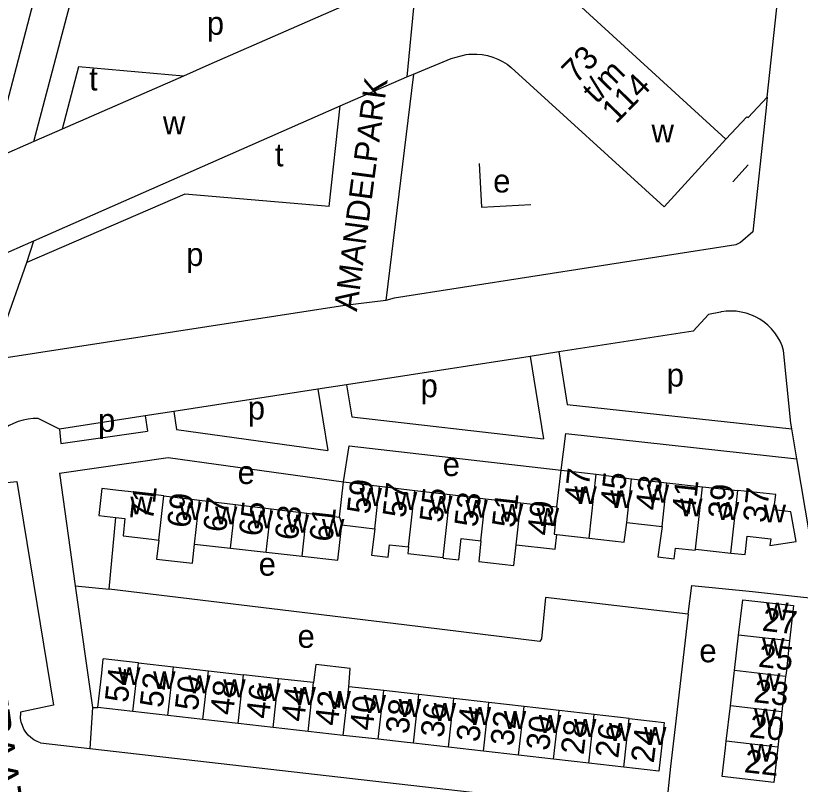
# Model space of a CAD drawing. Extents: x 161936 to 163647, y 386450 to 388633.
# Drawn here: x 162533 to 162668.3, y 387480.8 to 387613.3 of the extents above; entities that cross this region are included whole.
import ezdxf

# ---------------------------------------------------------------- set-up
doc = ezdxf.new("R2010")
doc.units = 0
for name, color, linetype in [('BLT_Basislijn', 7, 'Continuous'), ('BLT_Bebouwing', 7, 'Continuous'), ('BLT_Centroide', 7, 'Continuous'), ('BLT_Huisnummer', 7, 'Continuous'), ('BLT_Huisnummer_ tussenligend', 7, 'Continuous'), ('BLT_Huisnummer_reeks', 7, 'Continuous'), ('BLT_Onderdoorgang_en_onderverdeling', 7, 'Continuous'), ('BLT_Onderverdeling_panden', 7, 'Continuous'), ('BLT_Straatnaam', 7, 'Continuous')]:
    doc.layers.add(name, color=color, linetype=linetype)

msp = doc.modelspace()

# ---------------------------------------------------------------- linework, layer by layer
at = {"layer": 'BLT_Basislijn'}
for p, q in [((162536.08, 387615.52), (162528.92, 387588.41)), ((162536.17, 387591.57), (162542.39, 387615.1)), ((162601.58, 387603.19), (162596.84, 387564.21)), ((162662.59, 387599.2), (162662.34, 387596.81)), ((162587.07, 387580.38), (162588.95, 387597.75)), ((162659.31, 387587.57), (162656.64, 387584.62)), ((162534.98, 387570.76), (162536.17, 387574.5)), ((162589.75, 387563.33), (162531.07, 387554.28)), ((162598.3, 387564.58), (162596.84, 387564.21)), ((162626.67, 387555.34), (162621.73, 387554.57)), ((162626.67, 387555.34), (162628.12, 387546.26)), ((162666.65, 387543.07), (162665.41, 387555.55)), ((162621.73, 387554.57), (162590.08, 387549.67)), ((162621.73, 387554.57), (162624.01, 387540.35)), ((162585.14, 387548.91), (162560.3, 387545.06)), ((162590.08, 387549.67), (162585.14, 387548.91)), ((162585.14, 387548.91), (162586.84, 387538.35)), ((162590.08, 387549.67), (162590.98, 387544.12)), ((162628.12, 387546.26), (162666.83, 387542.05)), ((162560.3, 387545.06), (162555.36, 387544.29)), ((162560.3, 387545.06), (162560.78, 387541.95)), ((162540.58, 387542), (162536.91, 387543.84)), ((162555.36, 387544.29), (162540.58, 387542)), ((162555.36, 387544.29), (162555.77, 387541.65)), ((162590.98, 387544.12), (162624.01, 387540.35)), ((162666.83, 387542.05), (162666.65, 387543.07)), ((162540.58, 387542), (162540.8, 387539.54)), ((162540.8, 387539.54), (162555.77, 387541.65)), ((162560.78, 387541.95), (162586.84, 387538.35)), ((162667.58, 387537.62), (162666.83, 387542.05)), ((162667.69, 387536.93), (162667.58, 387537.62)), ((162671.73, 387512.76), (162667.69, 387536.93)), ((162540.58, 387534.46), (162543.32, 387515.03)), ((162549.13, 387514.43), (162550.31, 387526.81)), ((162543.32, 387515.03), (162549.13, 387514.43)), ((162546.28, 387494.08), (162545.8, 387487)), ((162537.32, 387487.97), (162545.8, 387487)), ((162545.8, 387487), (162645.04, 387475.7))]:
    msp.add_line(p, q, dxfattribs=at)
for points in [[(162662.59, 387599.2), (162664.43, 387616.29), (162664.43, 387616.59), (162664.41, 387616.86), (162664.24, 387617.31), (162664.05, 387617.6), (162663.88, 387617.77), (162663.51, 387618.06)], [(162561.96, 387602.82), (162543.89, 387604.46), (162541.04, 387593.7)], [(162655.45, 387591.98), (162659.04, 387595.86), (162659.27, 387595.71), (162662.59, 387599.2)], [(162662.34, 387596.81), (162660.11, 387576.01), (162657.99, 387574.17), (162657.14, 387573.79), (162598.3, 387564.58)], [(162612.93, 387587.79), (162613.33, 387580.26), (162621.83, 387580.71)], [(162587.07, 387580.38), (162562.21, 387582.54), (162534.98, 387570.76)], [(162531.07, 387554.28), (162530.95, 387559.32), (162534.98, 387570.76)], [(162596.84, 387564.21), (162589.75, 387563.33)], [(162654.5, 387562.19), (162652.46, 387561.78), (162649.81, 387558.93), (162626.67, 387555.34)], [(162665.41, 387555.55), (162665.13, 387556.38), (162664.78, 387557.17), (162664.36, 387557.93), (162663.87, 387558.64), (162663.32, 387559.31), (162662.7, 387559.92), (162662.03, 387560.47), (162661.32, 387560.97), (162660.56, 387561.39), (162659.77, 387561.74), (162658.95, 387562.01), (162658.1, 387562.21), (162657.24, 387562.33), (162656.38, 387562.38), (162655.51, 387562.34), (162654.65, 387562.22), (162654.5, 387562.19)], [(162536.91, 387543.84), (162536.04, 387543.83), (162535.17, 387543.74), (162534.32, 387543.58), (162533.49, 387543.34), (162532.68, 387543.02), (162531.9, 387542.63), (162531.16, 387542.17), (162530.47, 387541.64), (162529.83, 387541.05), (162529.25, 387540.41), (162528.73, 387539.71), (162528.27, 387538.97), (162527.88, 387538.19), (162527.57, 387537.38), (162527.33, 387536.55), (162527.18, 387535.69), (162527.13, 387535.27)], [(162627.07, 387534.97), (162627.86, 387541.26), (162667.69, 387536.93)], [(162589.53, 387532.92), (162590.51, 387539.15), (162627.07, 387534.97)], [(162540.58, 387534.46), (162559.33, 387537.11), (162589.53, 387532.92)], [(162527.13, 387535.27), (162527.33, 387532.42), (162533.24, 387533.03), (162539.56, 387494.49), (162533.85, 387493.27), (162533.85, 387492.66)], [(162543.32, 387515.03), (162546.28, 387494.08)], [(162648.95, 387510.13), (162649.61, 387515.1), (162660.06, 387514.06), (162668.81, 387513.1), (162671.73, 387512.76)], [(162648.95, 387510.13), (162624.34, 387512.99), (162623.67, 387505.88), (162623.4, 387505.46), (162600, 387508.29), (162549.13, 387514.43)], [(162648.95, 387510.13), (162646.83, 387491.72), (162645.91, 387483.89), (162645.04, 387475.7)], [(162546.28, 387494.08), (162547.19, 387494.06)], [(162537.32, 387487.97), (162536.73, 387488.2), (162536.17, 387488.51), (162535.66, 387488.89), (162535.2, 387489.32), (162534.8, 387489.82), (162534.46, 387490.35), (162534.19, 387490.93), (162534, 387491.53), (162533.89, 387492.16), (162533.85, 387492.66)]]:
    msp.add_lwpolyline(points, dxfattribs=at)
at = {"layer": 'BLT_Bebouwing'}
for p, q in [((162601.82, 387620.34), (162566.34, 387604.79)), ((162629.24, 387615.96), (162655.45, 387591.98)), ((162566.34, 387604.79), (162561.96, 387602.82)), ((162561.96, 387602.82), (162541.04, 387593.7)), ((162588.95, 387597.75), (162600.46, 387602.72)), ((162600.46, 387602.72), (162601.58, 387603.19)), ((162536.17, 387574.5), (162588.95, 387597.75)), ((162541.04, 387593.7), (162536.17, 387591.57)), ((162655.45, 387591.98), (162644.81, 387580.32)), ((162536.17, 387591.57), (162528.92, 387588.41)), ((162525.58, 387569.83), (162536.17, 387574.5)), ((162626.34, 387528.61), (162627.07, 387534.97)), ((162627.07, 387534.97), (162633.1, 387534.29)), ((162633.1, 387534.29), (162639.19, 387533.48)), ((162639.19, 387533.48), (162645.29, 387532.79)), ((162645.29, 387532.79), (162651.4, 387532.09)), ((162601.82, 387531.45), (162607.93, 387530.76)), ((162651.4, 387532.09), (162657.53, 387531.48)), ((162558.57, 387530.51), (162564.74, 387529.77)), ((162564.74, 387529.77), (162570.9, 387529.02)), ((162607.93, 387530.76), (162614.03, 387530.01)), ((162614.03, 387530.01), (162620.13, 387529.31)), ((162570.9, 387529.02), (162577.07, 387528.27)), ((162577.07, 387528.27), (162583.24, 387527.53)), ((162620.13, 387529.31), (162626.34, 387528.61)), ((162583.24, 387527.53), (162588.84, 387526.85)), ((162588.84, 387526.85), (162589.26, 387525.51)), ((162589.26, 387525.51), (162594.95, 387524.87)), ((162638.35, 387525.94), (162644.45, 387525.25)), ((162626.29, 387523.89), (162631.88, 387523.26)), ((162563.88, 387522.22), (162570.05, 387521.52)), ((162570.05, 387521.52), (162576.23, 387520.82)), ((162576.23, 387520.82), (162582.4, 387520.12)), ((162656.94, 387500.43), (162657.65, 387506.52)), ((162554.18, 387501.77), (162560.23, 387501.08)), ((162560.23, 387501.08), (162566.27, 387500.4)), ((162578.36, 387499.02), (162572.32, 387499.71)), ((162584.4, 387498.34), (162578.36, 387499.02)), ((162665.75, 387499.43), (162665.07, 387493.34)), ((162596.49, 387496.97), (162590.45, 387497.65)), ((162608.58, 387495.6), (162602.54, 387496.28)), ((162614.62, 387494.91), (162608.58, 387495.6)), ((162620.67, 387494.23), (162614.62, 387494.91)), ((162655.52, 387488.25), (162656.23, 387494.34)), ((162553.23, 387493.38), (162547.19, 387494.06)), ((162559.28, 387492.69), (162553.23, 387493.38)), ((162626.71, 387493.54), (162620.67, 387494.23)), ((162632.76, 387492.85), (162626.71, 387493.54)), ((162665.07, 387493.34), (162664.38, 387487.25)), ((162565.32, 387492.01), (162559.28, 387492.69)), ((162571.37, 387491.32), (162565.32, 387492.01)), ((162638.8, 387492.17), (162632.76, 387492.85)), ((162577.41, 387490.63), (162571.37, 387491.32)), ((162583.45, 387489.95), (162577.41, 387490.63)), ((162589.5, 387489.26), (162583.45, 387489.95)), ((162595.54, 387488.58), (162589.5, 387489.26)), ((162607.63, 387487.21), (162601.59, 387487.89)), ((162613.67, 387486.52), (162607.63, 387487.21)), ((162619.72, 387485.84), (162613.67, 387486.52)), ((162625.76, 387485.15), (162619.72, 387485.84)), ((162631.81, 387484.47), (162625.76, 387485.15)), ((162637.85, 387483.78), (162631.81, 387484.47))]:
    msp.add_line(p, q, dxfattribs=at)
for points in [[(162601.58, 387603.19), (162608.11, 387605.89), (162610.7, 387606.56), (162611.14, 387606.61)], [(162611.14, 387606.61), (162611.84, 387606.65), (162612.52, 387606.65), (162613.44, 387606.57), (162614.36, 387606.4), (162615.26, 387606.14), (162616.13, 387605.8), (162616.96, 387605.39), (162617.74, 387604.9), (162618.46, 387604.36), (162644.81, 387580.32)], [(162588.84, 387526.85), (162589.53, 387532.92)], [(162589.53, 387532.92), (162595.72, 387532.21)], [(162595.72, 387532.21), (162601.82, 387531.45)], [(162550.75, 387531.45), (162547.91, 387531.77), (162547.39, 387527.14), (162550.31, 387526.81)], [(162558.57, 387530.51), (162552.4, 387531.26), (162550.75, 387531.45)], [(162659.11, 387523.59), (162663.17, 387523.13), (162663.04, 387522), (162667.56, 387522.66), (162666.67, 387527.79), (162663.73, 387528.12), (162664.04, 387530.78), (162657.53, 387531.48)], [(162550.31, 387526.81), (162551.88, 387526.63), (162551.54, 387523.62), (162556.5, 387523.06), (162557.71, 387522.92)], [(162582.4, 387520.12), (162588.57, 387519.42), (162589.26, 387525.51)], [(162631.88, 387523.26), (162637.94, 387522.57), (162638.35, 387525.94)], [(162594.95, 387524.87), (162594.38, 387520.29), (162597.24, 387519.97), (162597.47, 387522.1), (162600.74, 387521.74)], [(162644.45, 387525.25), (162643.74, 387520.03), (162646.56, 387519.68), (162646.77, 387521.54), (162650.17, 387521.15), (162650.21, 387521.36)], [(162557.71, 387522.92), (162557.32, 387519.6), (162563.5, 387518.91), (162563.88, 387522.22)], [(162606.73, 387519.89), (162606.72, 387519.77), (162609.42, 387519.48), (162609.84, 387523.18), (162613.23, 387522.79)], [(162613.23, 387522.79), (162612.85, 387519.22), (162618.93, 387518.55), (162619.33, 387522.1)], [(162625.58, 387521.39), (162626, 387521.35), (162626.29, 387523.89)], [(162656.33, 387520.67), (162658.75, 387520.4), (162659.11, 387523.59)], [(162600.74, 387521.74), (162600.62, 387520.58), (162606.73, 387519.89)], [(162619.33, 387522.1), (162625.58, 387521.39)], [(162650.21, 387521.36), (162656.33, 387520.67)], [(162657.65, 387506.52), (162658.36, 387512.6), (162667.13, 387511.61)], [(162667.13, 387511.61), (162666.44, 387505.52)], [(162666.44, 387505.52), (162665.82, 387500), (162665.75, 387499.43)], [(162547.19, 387494.06), (162547.86, 387500), (162548.14, 387502.45)], [(162554.18, 387501.77), (162553.61, 387501.83), (162548.14, 387502.45)], [(162590.45, 387497.65), (162590.72, 387500.78), (162584.79, 387501.45), (162584.4, 387498.34)], [(162566.27, 387500.4), (162569.76, 387500), (162572.32, 387499.71)], [(162656.23, 387494.34), (162656.89, 387500), (162656.94, 387500.43)], [(162602.54, 387496.28), (162600, 387496.57), (162596.49, 387496.97)], [(162638.8, 387492.17), (162644.84, 387491.48), (162644.45, 387488.06), (162643.89, 387483.09)], [(162601.59, 387487.89), (162600, 387488.07), (162595.54, 387488.58)], [(162663.69, 387481.16), (162654.82, 387482.17), (162655.39, 387487.13), (162655.52, 387488.25)], [(162664.38, 387487.25), (162663.69, 387481.16)], [(162643.89, 387483.09), (162637.85, 387483.78)]]:
    msp.add_lwpolyline(points, dxfattribs=at)
at = {"layer": 'BLT_Onderdoorgang_en_onderverdeling'}
msp.add_line((162602.2, 387620.48), (162600.46, 387602.72), dxfattribs=at)
at = {"layer": 'BLT_Onderverdeling_panden'}
for p, q in [((162631.88, 387523.26), (162633.1, 387534.29)), ((162638.35, 387525.94), (162639.19, 387533.48)), ((162594.95, 387524.87), (162595.72, 387532.21)), ((162644.45, 387525.25), (162645.29, 387532.79)), ((162600.74, 387521.74), (162601.82, 387531.45)), ((162650.21, 387521.36), (162651.4, 387532.09)), ((162656.33, 387520.67), (162657.53, 387531.48)), ((162557.71, 387522.92), (162558.57, 387530.51)), ((162563.88, 387522.22), (162564.74, 387529.77)), ((162606.73, 387519.89), (162607.93, 387530.76)), ((162613.23, 387522.79), (162614.03, 387530.01)), ((162570.05, 387521.52), (162570.9, 387529.02)), ((162576.23, 387520.82), (162577.07, 387528.27)), ((162619.33, 387522.1), (162620.13, 387529.31)), ((162582.4, 387520.12), (162583.24, 387527.53)), ((162666.44, 387505.52), (162657.65, 387506.52)), ((162553.23, 387493.38), (162554.18, 387501.77)), ((162559.28, 387492.69), (162560.23, 387501.08)), ((162565.32, 387492.01), (162566.27, 387500.4)), ((162571.37, 387491.32), (162572.32, 387499.71)), ((162665.75, 387499.43), (162656.94, 387500.43)), ((162577.41, 387490.63), (162578.36, 387499.02)), ((162583.45, 387489.95), (162584.4, 387498.34)), ((162589.5, 387489.26), (162590.45, 387497.65)), ((162595.54, 387488.58), (162596.49, 387496.97)), ((162601.59, 387487.89), (162602.54, 387496.28)), ((162607.63, 387487.21), (162608.58, 387495.6)), ((162613.67, 387486.52), (162614.62, 387494.91)), ((162665.07, 387493.34), (162656.23, 387494.34)), ((162619.72, 387485.84), (162620.67, 387494.23)), ((162625.76, 387485.15), (162626.71, 387493.54)), ((162631.81, 387484.47), (162632.76, 387492.85)), ((162637.85, 387483.78), (162638.8, 387492.17)), ((162664.38, 387487.25), (162655.52, 387488.25))]:
    msp.add_line(p, q, dxfattribs=at)
msp.add_lwpolyline([(162626.34, 387528.61), (162625.85, 387523.94), (162626.29, 387523.89)], dxfattribs=at)

# ---------------------------------------------------------------- texts
at = {"layer": 'BLT_Centroide'}
for s, p in [('p', (162565.98, 387609.98)), ('t', (162545.69, 387600.38)), ('w', (162558.42, 387592.84)), ('w', (162642.63, 387591.42)), ('t', (162577.73, 387587.31)), ('e', (162615.34, 387582.8)), ('p', (162562.43, 387570.14)), ('p', (162645.25, 387549.36)), ('p', (162602.83, 387547.52)), ('p', (162573.04, 387543.68)), ('p', (162547.24, 387541.56)), ('e', (162606.64, 387533.94)), ('e', (162571.29, 387532.57)), ('w', (162629.34, 387529.11)), ('w', (162641.81, 387529.38)), ('w', (162592.31, 387528.81)), ('w', (162598.38, 387528.12)), ('w', (162635.53, 387528.41)), ('w', (162552.8, 387527.34)), ('w', (162561.22, 387526.36)), ('w', (162604.47, 387527.44)), ('w', (162610.55, 387526.75)), ('w', (162647.56, 387526.98)), ('w', (162653.88, 387526.39)), ('w', (162567.39, 387525.62)), ('w', (162616.67, 387526.06)), ('w', (162622.84, 387525.36)), ('w', (162661.95, 387525.94)), ('w', (162573.56, 387524.91)), ('w', (162579.73, 387524.19)), ('w', (162585.83, 387523.47)), ('e', (162574.92, 387516.77)), ('w', (162662.4, 387509.06)), ('e', (162581.62, 387504.34)), ('w', (162661.7, 387502.97)), ('e', (162650.88, 387501.85)), ('w', (162550.69, 387497.91)), ('w', (162556.73, 387497.22)), ('w', (162661, 387496.88)), ('w', (162562.78, 387496.53)), ('w', (162568.81, 387495.84)), ('w', (162574.86, 387495.17)), ('w', (162580.91, 387494.5)), ('w', (162586.95, 387493.81)), ('w', (162593, 387493.12)), ('w', (162599.05, 387492.44)), ('w', (162605.08, 387491.75)), ('w', (162611.12, 387491.06)), ('w', (162617.17, 387490.38)), ('w', (162660.3, 387490.81)), ('w', (162623.22, 387489.69)), ('w', (162629.27, 387489)), ('w', (162635.3, 387488.31)), ('w', (162641.34, 387487.62)), ('w', (162659.6, 387484.72))]:
    msp.add_text(s, height=4, dxfattribs=at).set_placement(p)
at = {"layer": 'BLT_Huisnummer'}
for s, rotation, p in [('45', 83.6972, (162637.74, 387528.49)), ('57', 83.3962, (162600.22, 387526.64)), ('41', 83.695, (162650.09, 387527.2)), ('71', 83.529, (162556.71, 387526.14)), ('53', 83.3972, (162612.59, 387525.03)), ('37', 83.5242, (162662.33, 387525.78)), ('49', 83.526, (162625.15, 387523.57)), ('65', 83.5248, (162575.43, 387523.44)), ('61', 83.5287, (162587.59, 387522.48)), ('27', 353.5611, (162661.57, 387507.32)), ('54', 83.5324, (162552.35, 387494.78)), ('48', 83.5309, (162570.51, 387492.63)), ('23', 353.5594, (162660.11, 387495)), ('44', 83.5293, (162582.76, 387491.5)), ('40', 83.5293, (162594.57, 387489.97)), ('36', 83.5278, (162606.77, 387488.75)), ('32', 83.5271, (162618.8, 387487.3)), ('28', 83.5193, (162630.93, 387485.81)), ('20', 353.5649, (162659.35, 387488.98)), ('24', 83.3511, (162643.02, 387484.39)), ('22', 353.5649, (162658.49, 387482.92))]:
    msp.add_text(s, height=4, rotation=rotation, dxfattribs=at).set_placement(p)
at = {"layer": 'BLT_Huisnummer_ tussenligend'}
for s, rotation, p in [('47', 83.6972, (162631.52, 387529.13)), ('43', 83.695, (162643.82, 387527.9)), ('59', 83.526, (162594.07, 387527.26)), ('39', 83.5242, (162656.28, 387526.44)), ('69', 83.526, (162563.07, 387524.88)), ('55', 83.526, (162606.59, 387525.79)), ('67', 83.526, (162569.29, 387524.14)), ('51', 83.526, (162619.07, 387524.92)), ('63', 83.526, (162581.64, 387522.76)), ('25', 353.5611, (162660.92, 387501.1)), ('52', 83.3511, (162558.37, 387493.9)), ('50', 83.3511, (162564.42, 387493.39)), ('46', 83.3511, (162576.69, 387492)), ('42', 83.3511, (162588.55, 387490.79)), ('38', 83.3511, (162600.74, 387489.39)), ('34', 83.3511, (162612.92, 387487.99)), ('30', 83.3511, (162624.95, 387486.52)), ('26', 83.3511, (162636.89, 387485.21))]:
    msp.add_text(s, height=4, rotation=rotation, dxfattribs=at).set_placement(p)
at = {"layer": 'BLT_Huisnummer_reeks'}
for s, p in [('73', (162629.63, 387601.42)), ('t/m', (162633.16, 387597.95)), ('114', (162636.53, 387594.52))]:
    msp.add_text(s, height=4, rotation=45.7678, dxfattribs=at).set_placement(p)
at = {"layer": 'BLT_Straatnaam'}
for s, height, rotation, p in [('AMANDELPARK', 4, 82.4427, (162591.85, 387562.2)), ('BOEKWEITSTRAAT', 5, 278.2054, (162520.68, 387536.97))]:
    msp.add_text(s, height=height, rotation=rotation, dxfattribs=at).set_placement(p)

doc.saveas('drawing.dxf')
